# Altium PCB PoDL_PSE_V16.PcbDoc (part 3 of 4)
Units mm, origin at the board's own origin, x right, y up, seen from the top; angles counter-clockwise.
Board outline 155 x 86.5 mm, 4 copper layers (Top Layer, Signal Layer 2, Signal Layer 3, Bottom Layer), stack 1.586 mm thick; 431 components, 281 nets, 1286 pads, 864 vias.
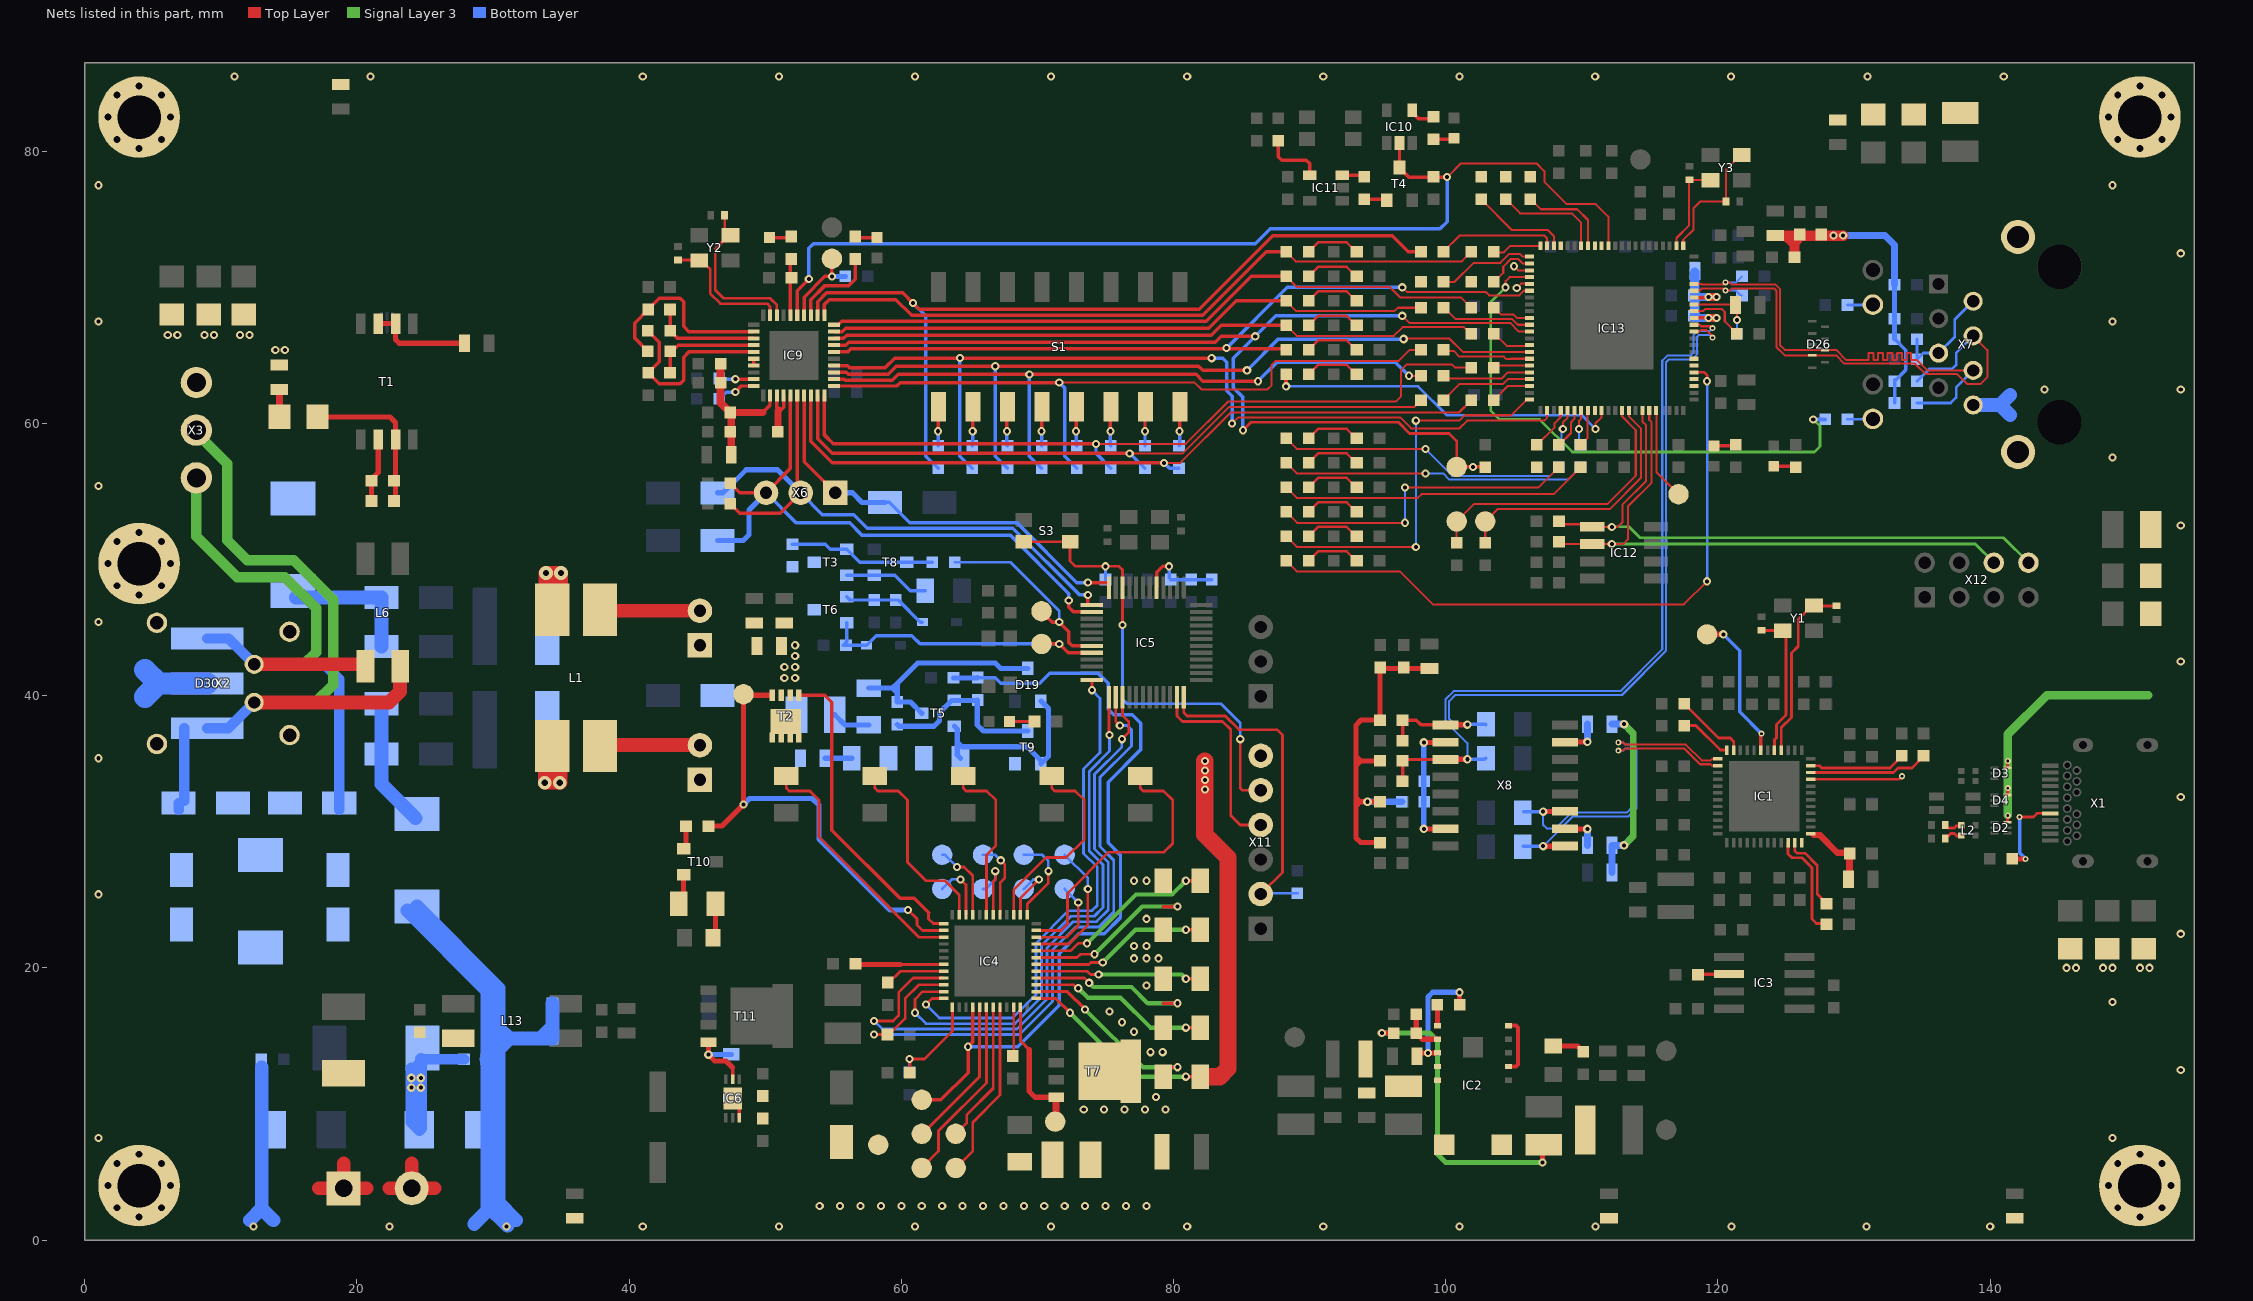
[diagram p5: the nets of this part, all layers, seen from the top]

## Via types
v1: diameter 0.6, hole 0.3, Top Layer to Bottom Layer, tented both sides, 494 vias
v2: diameter 0.45, hole 0.2, Top Layer to Bottom Layer, tented both sides, 173 vias
v3: diameter 0.635, hole 0.3, Top Layer to Bottom Layer, tented both sides, 145 vias
v4: diameter 1.016, hole 0.508, Top Layer to Bottom Layer, 40 vias
v5: diameter 1.016, hole 0.457, Top Layer to Bottom Layer, tented both sides, 8 vias
v6: diameter 0.762, hole 0.381, Top Layer to Bottom Layer, tented both sides, 4 vias

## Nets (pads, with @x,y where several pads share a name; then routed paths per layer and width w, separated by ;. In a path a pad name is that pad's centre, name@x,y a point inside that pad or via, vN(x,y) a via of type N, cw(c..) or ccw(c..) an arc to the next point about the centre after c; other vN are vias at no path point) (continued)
GPIO4: IC13.27 | length 1
  Top Layer w0.147: v1(105.218,69.945) 105.54,70.266 IC13.27@106.134,70.266
GPIO5: IC13.26 R91.2 | length 40.5
  Top Layer w0.152: v1(104.4,70) 104.4,70.45 104.7,70.75 IC13.26@106.15,70.75
  Signal Layer 3 w0.203: v1(104.4,70) 103.3,68.9 103.3,60.935 103.935,60.3 106.9,60.3 109.3,57.9 127.1,57.9 127.5,58.3 127.5,59.8 v1(127,60.3)
  Bottom Layer w0.3: v1(127,60.3) R91.2@127.874,60.3
GPIO6: IC13.14
GPIO7: IC13.13
HGATE0: HGATE0.1 IC4.2 R35.2 T2.4 | length 34.2
  Top Layer w0.203: v1(60.5,24.25) 61.141,23.608 61.141,23.158 61.55,22.75 IC4.2@63.1,22.75
  Top Layer w0.381: R35.2@45.825,30.4 45.8,30.425 46.825,30.425 v1(48.4,32) 48.4,40 48.5,40.1 48.57,40.03 T2.4@50.525,40.03
  Bottom Layer w0.381: v1@48.4,32.1 v1(48.4,32) 48.85,32.45 53.434,32.45 53.944,31.94 53.944,29.462 59.156,24.25 v1(60.5,24.25)
I2C2_SCL: IC12.6 IC13.61 R85.2 X12.6 | length 44.1
  Top Layer w0.152: R85.2@108.326,51.3 108.491,51.135 IC12.6@110.76,51.135 v1(112.2,51.135) 113.035,51.135 113.381,51.481 113.381,53.892 115.102,55.613 115.102,60.12 114.95,60.272 IC13.61@114.95,60.95
  Signal Layer 3 w0.203: v1(112.2,51.135) 138.905,51.135 X12.6@140.27,49.77
I2C2_SDA: IC12.5 IC13.60 R86.2 X12.8 | length 45.2
  Top Layer w0.152: IC12.5@111,52.405 112.645,52.405 113,52.76 113,54.05 114.721,55.771 114.721,59.874 114.45,60.145 IC13.60@114.45,60.95
  Top Layer w0.178: R86.2@108.326,52.8 108.526,52.6 IC12.5@110.565,52.6
  Signal Layer 3 w0.203: v1(112.2,52.4) 113.483,52.4 114.283,51.6 140.98,51.6 X12.8@142.81,49.77
I\N\T\: D7.2 IC5.14 IC9.25 R70.2 X6.3 | length 45.6
  Top Layer w0.254: R70.2@47.426,55.6 48.125,54.9 X6.3@50.06,54.9 51.85,56.69 IC9.25@51.85,62.05 ; v1(72.3,47) 72.3,46.496 72.646,46.15 IC5.14@73.975,46.15
  Bottom Layer w0.254: X6.3@50.06,54.9 52.26,52.7 56.2,52.7 57.1,51.8 68,51.8 72.3,47.5 v1(72.3,47)
  Bottom Layer w0.381: D7.2@46.5,51.4 48.38,51.4 48.8,51.82 48.8,53.64 X6.3@50.06,54.9 X6.3@50.06,54.36
IRQ: IC13.62 TP6.1 | length 6.8
  Top Layer w0.152: IC13.62@115.483,60.917 115.483,56.417 TP6.1@117.1,54.8
LED2: IC1.24
LED3: IC1.33 | length 6.8
  Top Layer w0.203: IC1.33@126.8,33.85 133.295,33.85 v2(133.525,34.08)
LINK_ST: IC9.4 R60.1 TP4.1 | length 6.3
  Top Layer w0.254: IC9.4@52.85,67.95 52.85,69.276 54.374,70.8 v1(54.9,70.8) TP4.1@54.9,72.1
  Bottom Layer w0.381: v1(54.9,70.8) R60.1@55.875,70.8
LSNS: C38.1 D9.1 IC4.26 IC4.28 IC4.31 LSNS.1 R24.1 RSL0.1 RSL1.1 RSL2.1 RSL3.1 RSL4.1 T7.mb | length 39
  Top Layer w0.203: IC4.28@69.9,19.25 73.45,19.25 v1(73.8,18.9) ; IC4.31@69.9,20.75 72.9,20.75 73.15,21 v1(74.2,21)
  Top Layer w0.229: IC4.26@69.9,18.25 72.2,18.25 v1(73.5,16.95)
  Top Layer w0.254: RSL0.1@79.25,12.7 v1(80.3,12.7) ; 79.25,17.4 v1(80.3,17.4) ; 79.25,24.5 v1(80.3,24.5)
  Signal Layer 3 w0.305: v1(73.5,16.95) 77.75,12.7 v1(80.3,12.7) ; v1(73.8,18.9) 74.1,18.6 76.9,18.6 78.1,17.4 v1(80.3,17.4) ; v1(74.2,21) 77.7,24.5 v1(80.3,24.5)
  other v1: 54,2.5 55.5,2.5 57,2.5 58.5,2.5 60,2.5 61.5,2.5 63,2.5 64.5,2.5 66,2.5 67.5,2.5 69,2.5 70.5,2.5 72,2.5 73.5,2.5 75,2.5 76.5,2.5 78,2.5 73.4,9.6 74.9,9.6 76.4,9.6 77.9,9.6 79.4,9.6 78.7,10.5 78.3,13.8 79.2,13.8 77.1,15.3 76.2,16 75.3,16.8 78,18.7 77.1,20.7 78,20.7 78.9,20.7 77.1,21.6 78,21.6 78,23.6 77.1,26.4 78,26.4
MDC: D6.2 IC5.12 IC9.27 X6.1 | length 31.2
  Top Layer w0.254: IC9.27@52.85,62.05 52.85,57.19 X6.1@55.14,54.9 ; v1(73.7,48.3) IC5.12@75.256,48.3
  Bottom Layer w0.254: D6.2@58.8,54.2 59.125,54.2 60.625,52.7 68.5,52.7 72.9,48.3 v1(73.7,48.3)
  Bottom Layer w0.381: X6.1@55.14,55.15 X6.1@55.14,54.9 ; X6.1@55.145,54.895 X6.1@55.14,54.9 ; D6.2@58.8,54.2 57.1,54.2 56.4,54.9 X6.1@55.14,54.9
MDIO: D8.2 IC5.13 IC9.26 R71.2 X6.2 | length 45.8
  Top Layer w0.254: R71.2@47.426,54.1 48.126,53.4 51.1,53.4 X6.2@52.6,54.9 ; X6.2@52.35,54.8 IC9.26@52.35,62.05 ; IC5.13@73.7,46.65 v1(73.7,47.4)
  Bottom Layer w0.254: X6.2@52.6,54.9 54.2,53.3 56.5,53.3 57.5,52.3 68.186,52.3 73.086,47.4 v1(73.7,47.4)
  Bottom Layer w0.381: D8.2@46.5,54.9 46.9,54.9 48.6,56.6 50.9,56.6 X6.2@52.6,54.9
NetC1_2: C1.2 IC4.7 | length 6.5
  Top Layer w0.203: 59.924,20.25 IC4.7@63.1,20.25
  Top Layer w0.381: C1.2@56.625,20.3 56.675,20.25 59.924,20.25
NetC7_1: C7.1 L2.3 | length 1.3
  Top Layer w0.206: C7.1@136.7,30.5 136.93,30.27 137.372,30.27 137.547,30.445 L2.3@137.875,30.445
NetC8_1: C8.1 L2.2 | length 1.4
  Top Layer w0.206: C8.1@136.7,29.47 137.1,29.87 137.372,29.87 137.547,29.695 L2.2@137.875,29.695
NetC9_1: C9.1 FB3.1 IC1.25 | length 8
  Top Layer w0.254: C9.1@129.374,28.355 128.725,28.355 127.419,29.661 126.989,29.661 IC1.25@126.8,29.85 127.536,29.85 128.806,28.58 C9.1@129.5,28.58
  Top Layer w0.508: FB3.1@129.675,26.805 C9.1@129.675,28.405
NetC26_1: C26.1 C123.1 IC2.4 IC2.5 L11.2
NetC29_1: C29.1 IC1.48 | length 4
  Top Layer w0.2: C29.1@117.426,37.805 118.37,37.805 120.175,36 IC1.48@120.65,36
NetC30_2: C30.2 IC1.40 Y1.1 | length 13.2
  Top Layer w0.203: IC1.40@124.65,36 124.65,37.654 125.4,38.404 125.4,43.13 125.9,43.63 125.9,45.605 Y1.1@126.8,46.505 ; Y1.1@126.9,46.58 C30.2@128.7,46.58
NetC31_2: C31.2 IC1.41 Y1.3 | length 10.7
  Top Layer w0.203: C31.2@123.2,44.78 Y1.3@124.725,44.78 ; IC1.41@124.15,36 124.15,36.755 124.3,36.905 124.3,37.87 125,38.57 Y1.3@125,44.805
NetC32_1: C32.1 IC4.8 | length 4.3
  Top Layer w0.203: C32.1@59.1,18.925 59.924,19.75 IC4.8@63.1,19.75
NetC33_1: C33.1 C119.1 T1.6 | length 4.7
  Top Layer w0.381: C119.1@21.074,54.3 C33.1@21.074,55.8 21.074,55.909 21.565,56.4 T1.6@21.565,58.82
NetC33_2: C33.2 C42.1 C119.2 T1.7 | length 11.8
  Top Layer w0.381: C42.1@17.1,60.1 17.47,60.47 22.435,60.47 22.835,60.07 T1.7@22.835,58.82 C119.2@22.835,54.3
NetC34_2: C34.2 R13.1 | length 2
  Bottom Layer w0.381: C34.2@54.4,35.4 R13.1@56.35,35.4
NetC35_2: C35.2 R14.1 | length 2.8
  Bottom Layer w0.381: C35.2@55.1,38.6 55.85,37.85 R14.1@57.6,37.85
NetC36_1: C36.1 R27.1 T3.1 T8.3 | length 10.8
  Bottom Layer w0.254: C36.1@52,51.126 54.4,51.126 54.776,50.75 T3.1@56,50.75 56.95,49.8 T8.3@60.4,49.8 R27.1@62.275,49.8
NetC37_1: C37.1 T1.2 T1.3 | length 7.6
  Top Layer w0.381: T1.3@21.57,67.341 22.84,67.341 22.84,66.156 23.105,65.891 C37.1@27.9,65.891
NetC38_2: C38.2 R25.1
NetC39_1: C39.1 R30.2 T5.1 T9.3 | length 12.8
  Bottom Layer w0.381: C39.1@59.7,37.875 59.824,37.75 62.4,37.75 62.8,38.15 62.8,38.75 63.7,39.65 T5.1@63.9,39.65 R30.2@65.575,39.65 ; R30.2@65.6,39.675 R30.2@65.575,39.65 ; T9.3@69.3,37.4 66.025,37.4 65.575,37.85 R30.2@65.575,39.65
NetC39_2: C39.2 D19.3 R14.2 T5.3 | length 16.6
  Bottom Layer w0.381: R14.2@57.6,40.55 59.35,40.55 ; T5.3@61.5,38.7 60.674,39.526 C39.2@59.7,39.526 59.7,40.2 ; D19.3@69.3,42 67.3,42 66.9,42.4 61.2,42.4 59.7,40.9 ; 59.35,40.55 59.7,40.2 ; 59.35,40.55 59.7,40.9 ; 59.7,40.2 59.7,40.9
NetC42_2: C42.2 R42.1 | length 2
  Top Layer w0.508: C42.2@14.3,60.5 R42.1@14.3,62.5
NetC45_1: C45.1 C52.1 FB9.1 IC5.5 | length 6.3
  Top Layer w0.254: IC5.5@78.75,47.925 78.75,49.05 79.2,49.5 v1(79.675,49.5)
  Bottom Layer w0.254: v1(79.675,49.5) 79.675,48.651 C45.1@79.8,48.526 C52.1@81.3,48.526 FB9.1@82.8,48.526
NetC55_2: C55.2 IC9.8 Y2.1 | length 11.9
  Top Layer w0.203: C55.2@47.025,75.3 47.025,74.25 Y2.1@47.45,73.825 47.325,73.825 46.325,72.825 46.325,69.8 46.925,69.2 50.35,69.2 50.85,68.7 IC9.8@50.85,67.95
NetC56_2: C56.2 IC9.9 Y2.3 | length 9.8
  Top Layer w0.203: C56.2@43.6,72 Y2.3@45.3,72 ; Y2.3@45.325,71.975 45.95,71.35 45.95,69.55 46.7,68.8 50.15,68.8 50.35,68.6 IC9.9@50.35,67.95
NetC57_1: C57.1 C58.1 C63.1 C64.1 FB1.2 IC9.16 IC9.17 IC9.22 | length 11.3
  Top Layer w0.254: IC9.17@49.15,64.25 IC9.16@49.15,64.75 ; 49.825,60.8 50.35,61.325 IC9.22@50.35,62.05
  Top Layer w0.508: C63.1@47.426,60.8 49.825,60.8
  Top Layer w0.584: C58.1@46.725,64.4 C57.1@46.725,63 46.725,61.5 C63.1@47.426,60.8 ; FB1.2@47.5,57.7 C63.1@47.5,60.726
NetC59_1: C59.1 IC9.19 | length 2.5
  Top Layer w0.254: v1(47.8,63.25) IC9.19@49.15,63.25
  Bottom Layer w0.254: C59.1@46.675,63.25 v1(47.8,63.25)
NetC60_1: C60.1 IC9.20 | length 2.9
  Top Layer w0.254: v1(47.8,62.3) 48.25,62.75 IC9.20@49.15,62.75
  Bottom Layer w0.254: C60.1@46.625,61.8 47.125,62.3 v1(47.8,62.3)
NetC65_1: C65.1 IC9.23 IC9.24 | length 4
  Top Layer w0.254: IC9.23@50.85,62.05 50.85,61.15 51,61 51.174,61 51.35,61.176 IC9.24@51.35,62.05
  Top Layer w0.508: C65.1@50.926,59.4 50.925,60.926 51,61
NetC77_1: C77.1 FB2.2 IC13.81 | length 5.1
  Top Layer w0.152: IC13.81@118.258,68.75 FB2.2@121.25,68.75 ; FB2.2@121.374,68.8 121.4,68.775 v1(121.4,67.6)
  Bottom Layer w0.152: C77.1@121.4,66.726 v1(121.4,67.6)
NetC80_1: C80.1 C81.1 FB5.1 IC13.79 IC13.82 | length 9.9
  Top Layer w0.254: IC13.79@118.308,67.75 v1(119.3,67.75) ; IC13.82@118.308,69.25 v1@119.3,69.25
  Top Layer w0.6: v1(119.3,67.75) v1(119.9,67.75) ; v1(119.3,69.3) v1(119.9,69.3)
  Bottom Layer w0.6: C81.1@118.225,67.8 118.275,67.75 v1(119.3,67.75) v1(119.9,67.75) ; C80.1@118.225,69.3 118.275,69.25 C80.1@118.3,69.25 ; C80.1@118.3,69.3 v1(119.3,69.3) v1(119.9,69.3)
  Bottom Layer w0.7: C81.1@118.225,67.8 118.3,67.875 118.3,69.25 FB5.1@118.3,71.1
NetC82_2: C82.2 IC13.1 Y3.1 | length 9.5
  Top Layer w0.152: IC13.1@117.45,73.05 117.45,73.483 118.203,74.236 118.203,75.82 118.683,76.3 C82.2@120.6,76.3 120.6,78.65 Y3.1@121.675,79.725
NetC83_2: C83.2 IC13.2 Y3.3 | length 6.8
  Top Layer w0.152: IC13.2@116.95,73.05 116.95,73.623 117.879,74.552 C83.2@117.879,77.9 ; C83.2@117.9,77.9 Y3.3@119.425,77.9
NetC89_1: C89.1 R81.1 X7.P2 X7.P5 | length 8.2
  Bottom Layer w0.203: R81.1@134.625,66.2 C89.1@134.625,64.7 135.09,65.165 X7.P5@136.21,65.165 ; X7.P5@136.145,65.1 X7.P5@136.21,65.165 ; X7.P2@138.75,68.975 137.4,67.625 137.4,66.355 X7.P5@136.21,65.165
NetC97_2: C97.2 C107.1 D1.1 D29.1 L13.1 X4.2 | length 19.8
  Top Layer w1.016: 22.4,3.8 X4.2@24.025,3.8 ; 24.025,5.625 X4.2@24.025,3.8 ; 25.7,3.8 X4.2@24.025,3.8
  Bottom Layer w0.762: D1.1@24.975,13.279 C107.1@27.875,13.279
  Bottom Layer w0.889: D1.1@24,12.6 24,12.3 ; D1.1@24.7,13.3 D1.1@24.7,13 ; D1.1@24.8,13.1 D1.1@24.7,13 ; v3(24,11.2) v3(24,11.9) 24,12.3 ; v3(24,11.2) v3(24.7,11.2) ; v3(24,11.2) 24,8.69 D29.1@24.59,8.1 24.7,8.21 v3(24.7,11.2) ; 24,12.3 D1.1@24.7,13 ; v3(24.7,11.2) v3(24.7,11.9) D1.1@24.7,13
NetC98_1: C98.1 R153.1 X8.10 X8.15 | length 9.5
  Top Layer w0.381: v3(98.389,30.206) X8.15@99.971,30.206 ; v3(98.389,36.556) X8.10@99.971,36.556
  Bottom Layer w0.381: v3(98.389,30.206) v3(98.389,36.556)
NetC103_1: C103.1 R158.1 R159.1 | length 13.3
  Signal Layer 3 w0.508: v3(113.101,29) 113.776,29.675 113.776,37.225 v3(113.101,37.9)
  Bottom Layer w0.508: C103.1@112.201,27 R158.1@112.201,29 ; R158.1@112.2,29 v3(113.101,29) ; R159.1@112.2,37.9 v3(113.101,37.9)
NetC111_2: C111.2 FB10.2 X5.1
NetC112_1: C112.1 C113.1 C126.1 R77.2 R78.2 R79.2 R80.2 R81.2 R162.2 | length 24.9
  Top Layer w0.762: C126.1@124.2,73.8 124.997,73.8 ; R162.2@125.625,72.2 125.625,73.5 125.461,73.336 124.997,73.8 ; 125.7,73.4 C112.1@126,73.7 ; C112.1@126,73.875 C112.1@125.925,73.8 ; v1(129.2,73.8) v1(128.5,73.8) 127.6,73.8 C112.1@125.925,73.8 ; 124.997,73.8 C112.1@125.925,73.8
  Bottom Layer w0.254: R80.2@132.974,61.5 R79.2@132.974,63.1 ; R79.2@132.974,63.2 R79.2@132.974,63.1 ; R81.2@132.974,66.2 133.8,65.375 133.8,63.925 R79.2@132.974,63.1
  Bottom Layer w0.381: R81.2@132.974,66.2 R78.2@132.974,67.7 R77.2@132.974,70.2
  Bottom Layer w0.508: v1(128.5,73.8) v1(129.2,73.8) 132.283,73.8 132.974,73.109 R77.2@132.974,70.2
NetC114_1: C114.1 C115.1 FB8.1 R153.2 R154.2 R155.2 R156.2 R157.2 | length 26.7
  Top Layer w0.381: R154.2@95.175,29.2 93.751,29.2 93.401,29.55 93.401,31.9 ; R155.2@95.175,32.2 v3(94.251,32.2) 93.701,32.2 ; R156.2@95.175,35.2 93.751,35.2 ; C114.1@95.175,41.949 95.175,38.2 93.779,38.2 93.401,37.821 93.401,35.55 ; C114.1@95.275,42 FB8.1@98.8,42 ; 93.401,31.9 93.701,32.2 ; 93.401,31.9 93.401,32.5 ; 93.401,32.5 93.401,34.85 ; 93.401,32.5 93.701,32.2 ; 93.401,34.85 93.751,35.2 ; 93.401,34.85 93.401,35.55 ; 93.401,35.55 93.751,35.2
  Bottom Layer w0.508: v3(94.251,32.2) R153.2@96.775,32.2
NetC117_1: C117.1 D14.1 R31.2 T6.1 | length 6.3
  Bottom Layer w0.254: T6.1@56,47.25 56.224,47.026 C117.1@58,47.026 R31.2@59.6,47.026 59.775,47.026 61.4,45.4 D14.1@61.55,45.4
NetC122_2: C122.2 IC6.6 IC6.7 R43.1 | length 1.6
  Top Layer w0.254: IC6.7@47.6,10.4 48.1,9.9 IC6.6@48.1,9
NetC124_1: C124.1 IC2.6 IC2.7 L12.1 R10.2 | length 22.8
  Top Layer w0.381: v1(95.3,15.2) R10.2@96.174,15.2 ; v1(107.1,5.7) 107.1,6.9 C124.1@107.2,7
  Signal Layer 3 w0.381: v1(95.3,15.2) 98.8,15.2 99.4,14.6 99.4,6.3 100,5.7 v1(107.1,5.7)
NetC125_1: C125.1 IC2.3 R28.2 | length 9.1
  Top Layer w0.381: C125.1@97.9,13.5 98.15,13.75 v1(98.7,13.75) IC2.3@99.4,13.75 ; v1(101,18.2) 101,17.325 R28.2@101.026,17.3
  Bottom Layer w0.381: v1(98.7,13.75) 98.7,17.856 99.044,18.2 v1(101,18.2)
NetD5_2: D5.2 R4.2 | length 2.4
  Top Layer w0.381: D5.2@107.9,14.25 109.676,14.25 R4.2@110.1,13.825
NetD11_1: D11.1 D13.2 D16.1
NetD12_2: D12.2 D13.1 D15.2
NetD19_1: D19.1 R32.1 T5.2 T9.1 | length 14.5
  Bottom Layer w0.381: T5.2@63.9,37.75 64.1,37.55 64.1,36.6 ; R32.1@64.35,35.4 64.1,35.65 64.1,36.6 ; D19.1@70.25,39.6 70.8,39.05 70.8,35.55 T9.1@70.25,35 70.25,35.212 69.222,36.24 64.46,36.24 64.1,36.6
NetD20_2: D20.2 R36.1 | length 2.6
  Top Layer w0.381: D20.2@46.15,22.2 46.35,22.4 R36.1@46.35,24.7
NetD21_2: D21.2 R40.2 | length 1.7
  Top Layer w0.254: D21.2@68.05,38.1 R40.2@69.775,38.1
NetD23_1: D23.1 R62.1 | length 1.5
  Top Layer w0.254: D23.1@50.3,73.65 R62.1@51.825,73.65
NetD24_1: D24.1 R63.2 | length 1.5
  Top Layer w0.254: R63.2@56.675,73.65 D24.1@58.2,73.65
NetD25_2: D25.2 R74.2 | length 1.4
  Top Layer w0.254: R74.2@99.1,80.875 D25.2@100.525,80.875
NetD27_2: D27.2 R92.2 | length 1.6
  Top Layer w0.25: D27.2@124.1,56.85 125.624,56.85 R92.2@125.7,56.775
NetD28_2: D28.2 R93.2 | length 1.5
  Top Layer w0.25: D28.2@119.7,58.35 R93.2@121.224,58.35
NetD31_2: D31.2 D32.1 D33.2 | length 9.9
  Bottom Layer w1.016: D33.2@15.5,47.2 D31.2@21.8,47.2 D32.1@21.8,43.6
NetD34_2: D34.2 D35.1 D36.2 | length 9.4
  Bottom Layer w1.016: D34.2@21.8,39.4 D35.1@21.8,35.7 21.8,33.496 D36.2@24.3,30.996
NetF1_1: F1.1 X4.1 | length 5.3
  Top Layer w1.016: 17.2,3.8 X4.1@19.025,3.8 ; 19.025,5.625 X4.1@19.025,3.8 ; 20.7,3.8 X4.1@19.025,3.8
NetHGATE1_1: HGATE1.1 IC4.46 | length 4.4
  Top Layer w0.203: v1(64.35,26.5) 64.75,26.1 IC4.46@64.75,23.9
  Bottom Layer w0.203: HGATE1.1@63,25.8 63.7,26.5 v1(64.35,26.5)
NetHGATE2_1: HGATE2.1 IC4.42 | length 4.9
  Top Layer w0.203: IC4.42@66.75,23.9 66.75,26.35 66.944,26.544 v1@66.944,26.956
  Bottom Layer w0.203: HGATE2.1@66,25.8 66.2,25.8 66.9,26.5 v1(66.9,27.1)
NetHGATE3_1: HGATE3.1 IC4.38 | length 4.5
  Top Layer w0.203: IC4.38@68.75,23.9 68.75,25.125 70.1,26.475 v1(70.1,26.5)
  Bottom Layer w0.203: HGATE3.1@69,25.8 69.7,26.5 v1(70.1,26.5)
NetHGATE4_1: HGATE4.1 IC4.34 | length 6.6
  Top Layer w0.203: IC4.34@69.9,22.25 72.14,22.25 73,23.11 v1(73,24.8)
  Bottom Layer w0.203: HGATE4.1@72,25.8 v1(73,24.8)
NetIC1_23: IC1.23 R5.2 | length 5.8
  Top Layer w0.203: IC1.23@125.65,29.2 125.65,28.586 125.811,28.425 126.399,28.425 127.288,27.536 127.288,25.442 R5.2@127.975,24.755
NetIC1_35: IC1.35 R6.2 | length 7.2
  Top Layer w0.203: IC1.35@126.8,34.85 127.45,34.85 127.62,34.68 132.651,34.68 R6.2@133.525,35.555
NetIC1_47: IC1.47 R7.1 | length 5.4
  Top Layer w0.2: R7.1@117.526,39.4 120.045,36.881 120.905,36.881 121.15,36.635 IC1.47@121.15,36
NetIC2_1: IC2.1 R28.1 | length 1.6
  Top Layer w0.381: R28.1@99.275,17.3 R28.1@99.3,17.274 ; IC2.1@99.4,15.75 R28.1@99.4,17.274
NetIC2_2: IC2.2 R10.1 R34.1 | length 3.2
  Top Layer w0.381: R34.1@97.825,16.6 R10.1@97.825,15.2 98.276,14.75 IC2.2@99.4,14.75
NetIC2_9: IC2.9 IC2.12 | length 4.2
  Top Layer w0.305: IC2.9@104.6,12.75 105.15,12.75 105.3,12.9 105.3,15.6 105.15,15.75 IC2.12@104.6,15.75
NetIC3_6: IC3.6 R17.1 | length 2.2
  Top Layer w0.254: R17.1@118.56,19.535 IC3.6@120.8,19.535
NetIC4_3: IC4.3 RSH0.2 T2.mb | length 18.6
  Top Layer w0.203: RSH0.2@51.55,34.1 51.55,33.2 51.75,33 53.27,33 53.944,32.326 53.944,29.606 61.3,22.25 IC4.3@63.1,22.25
NetIC4_13: IC4.13 R37.2 R38.2 | length 7.6
  Top Layer w0.203: v1@60.589,13.3 61.7,13.3 63.75,15.35 IC4.13@63.75,17.1 ; R37.2@60.625,12.3 v1@60.625,13.163
  Bottom Layer w0.203: v1(60.6,13.3) 60.6,12.426 R38.2@60.7,12.326
NetIC4_16: IC4.16 R16.2 R30.1 SW0.1 | length 59.1
  Top Layer w0.254: SW0.1@61.5,10.3 62.9,10.3 64.9,12.3 v1(64.9,14.2) 65.25,14.55 IC4.16@65.25,17.1
  Bottom Layer w0.254: v1(64.9,14.2) 68.562,14.2 71.6,17.238 71.6,21.05 73.042,22.492 74.892,22.492 76.1,23.7 76.1,28.268 75.186,29.182 75.186,33.636 77.589,36.039 77.589,37.974 76.963,38.6 75.6,38.6 75.2,39 75.2,40.9 74.45,41.65 70.912,41.65 70.162,40.9 67.311,40.9 66.886,41.326 R30.1@65.6,41.326
  Bottom Layer w0.381: R16.2@63.825,41.3 65.574,41.3 R30.1@65.6,41.326
NetIC4_17: IC4.17 SW1.1 | length 11.1
  Top Layer w0.203: SW1.1@61.525,7.775 65.75,12 IC4.17@65.75,17.1
NetIC4_18: IC4.18 SW2.1 | length 13.8
  Top Layer w0.203: SW2.1@61.5,5.3 62.73,6.53 62.73,8.03 66.25,11.55 IC4.18@66.25,17.1
NetIC4_19: IC4.19 SW3.1 | length 10.4
  Top Layer w0.203: SW3.1@64,7.8 64.8,8.6 64.8,9.2 66.75,11.15 IC4.19@66.75,17.1
NetIC4_20: IC4.20 SW4.1 | length 13.1
  Top Layer w0.203: SW4.1@64,5.3 65.25,6.55 65.25,8.65 67.25,10.65 IC4.20@67.25,17.1
NetIC4_22: IC4.22 R9.1 | length 3.6
  Top Layer w0.203: R9.1@68.25,13.5 IC4.22@68.25,17.1
NetIC4_23: IC4.23 LGATE.1 T7.4 | length 10.4
  Top Layer w0.229: IC4.23@68.75,17.1 68.75,14.64 69.397,13.993
  Top Layer w0.381: 69.397,13.993 69.397,10.923 69.825,10.495 T7.4@71.375,10.495
  Top Layer w0.508: LGATE.1@71.3,8.7 71.375,8.775 T7.4@71.375,10.495
NetIC4_27: IC4.27 RSL1.2 | length 13.4
  Top Layer w0.203: IC4.27@69.9,18.75 72.65,18.75 v1@73,18.4
  Top Layer w0.254: v1(80.9,15.6) RSL1.2@81.95,15.6
  Signal Layer 3 w0.305: v1(73,18.5) 73.7,17.8 76.1,17.8 78.3,15.6 v1(80.9,15.6)
NetIC4_29: IC4.29 RSL2.2 | length 12.3
  Top Layer w0.203: IC4.29@69.9,19.75 73.654,19.75 73.904,19.5 v1(74.5,19.5)
  Top Layer w0.254: v1(80.9,19.2) RSL2.2@81.95,19.2
  Signal Layer 3 w0.305: v1(74.5,19.5) 80.6,19.5 v1(80.9,19.2)
NetIC4_30: IC4.30 RSL3.2 | length 13.1
  Top Layer w0.203: IC4.30@69.9,20.25 73.771,20.25 73.921,20.4 v1(74.8,20.4)
  Top Layer w0.254: v1(80.9,22.8) RSL3.2@81.95,22.8
  Signal Layer 3 w0.305: v1(74.8,20.4) 77.2,22.8 v1(80.9,22.8)
NetIC4_32: IC4.32 RSL4.2 | length 14.2
  Top Layer w0.203: IC4.32@69.9,21.25 72.44,21.25 72.99,21.8 v1(73.65,21.8)
  Top Layer w0.254: v1(80.9,26.4) RSL4.2@81.95,26.4
  Signal Layer 3 w0.305: v1(73.65,21.8) 77.25,25.4 79.9,25.4 v1(80.9,26.4)
NetIC4_33: IC4.33 OUTP4.1 | length 10.2
  Top Layer w0.203: IC4.33@69.9,21.75 72.3,21.75 73.7,23.15 v1(73.7,25.8)
  Bottom Layer w0.203: OUTP4.1@72,28.3 73.7,26.6 v1(73.7,25.8)
NetIC4_35: IC4.35 RSH4.2 | length 20.9
  Top Layer w0.203: IC4.35@69.9,22.75 71.74,22.75 72.2,23.21 72.2,25.474 75.225,28.5 79.3,28.5 79.944,29.144 79.944,32.326 79.27,33 77.75,33 77.55,33.2 RSH4.2@77.55,34.1
NetIC4_37: IC4.37 OUTP3.1 | length 6.8
  Top Layer w0.203: IC4.37@69.25,23.9 69.25,24.675 70.8,26.225 70.8,26.957 70.657,27.1 v1(70.8,27.1)
  Bottom Layer w0.203: OUTP3.1@69,28.3 70.355,28.3 70.8,27.855 v1(70.8,27.1)
NetIC4_39: IC4.39 RSH3.2 | length 15.1
  Top Layer w0.203: IC4.39@68.25,23.9 68.25,25.724 70.625,28.1 72.107,28.1 73.444,29.436 73.444,32.326 72.77,33 71.25,33 71.05,33.2 RSH3.2@71.05,34.1
NetIC4_41: IC4.41 OUTP2.1 | length 5.7
  Top Layer w0.203: IC4.41@67.25,23.9 67.274,23.924 67.274,26.274 67.6,26.6 67.6,27.6 v1(67.3,27.9)
  Bottom Layer w0.203: OUTP2.1@66,28.3 66.9,28.3 v1(67.3,27.9)
NetIC4_43: IC4.43 RSH2.2 | length 12.4
  Top Layer w0.203: RSH2.2@64.55,34.1 64.55,33.2 64.75,33 66.27,33 66.944,32.326 66.944,28.994 66.25,28.3 IC4.43@66.25,23.9
NetIC4_45: IC4.45 OUTP1.1 | length 5.8
  Top Layer w0.203: v1(64.1,27.4) 64.617,27.4 65.25,26.767 IC4.45@65.25,23.9
  Bottom Layer w0.203: OUTP1.1@63,28.3 63.2,28.3 v1(64.1,27.4)
NetIC4_47: IC4.47 RSH1.2 | length 14.5
  Top Layer w0.203: RSH1.2@58.05,34.1 58.05,33.2 58.25,33 59.77,33 60.444,32.326 60.444,27.756 61.8,26.4 63.207,26.4 64.25,25.357 IC4.47@64.25,23.9
NetIC6_2: IC6.2 T11.4 Z1.1 | length 5.6
  Top Layer w0.254: IC6.2@47.6,11.8 47.6,12.675
  Top Layer w0.381: T11.4@45.825,14.545 v3(45.825,13.625) 46.287,13.163 47.112,13.163 47.6,12.675
  Bottom Layer w0.381: v3(45.825,13.625) 47.488,13.625 Z1.1@47.5,13.638
NetIC9_3: IC9.3 R63.1 | length 6.5
  Top Layer w0.254: IC9.3@53.35,67.95 53.35,69.1 54.35,70.1 56.1,70.1 56.6,70.6 R63.1@56.6,72.075
NetIC9_6: IC9.6 R61.1 R62.2 | length 4.1
  Top Layer w0.254: IC9.6@51.85,67.95 R62.2@51.85,72.025
NetIC9_12: IC9.12 R64.2 R66.1 | length 14.1
  Top Layer w0.254: R66.1@41.374,65.3 40.4,66.275 40.4,67.375 R64.2@41.4,68.375 42.225,69.2 43.735,69.2 44,68.935 44,67.125 44.375,66.75 IC9.12@49.15,66.75
NetIC9_13: IC9.13 R65.2 R67.1 | length 7.6
  Top Layer w0.254: R67.1@43.025,66.8 R65.2@43.025,68.349 ; R67.1@43.2,66.6 43.55,66.25 IC9.13@49.15,66.25
NetIC9_14: IC9.14 R66.2 R68.2 | length 7.7
  Top Layer w0.254: R68.2@43.025,63.751 R66.2@43.025,65.3 ; R66.2@43.15,65.3 43.6,65.75 IC9.14@49.15,65.75
NetIC9_15: IC9.15 R67.2 R69.2 | length 13.8
  Top Layer w0.254: R67.2@41.374,66.8 42.2,65.974 42.2,64.526 R69.2@41.4,63.726 42.226,62.9 43.735,62.9 44,63.165 44,64.864 44.386,65.25 IC9.15@49.15,65.25
NetIC10_4: IC10.4 R74.1 | length 1.6
  Top Layer w0.254: IC10.4@97.55,82.85 98,82.4 R74.1@98.975,82.4
NetIC11_3: IC11.3 R76.1 | length 1.5
  Top Layer w0.254: IC11.3@92.4,78.25 R76.1@93.875,78.25
NetIC11_4: IC11.4 R75.2 | length 4.5
  Top Layer w0.254: R75.2@87.7,80.775 87.7,79.6 87.95,79.35 89.75,79.35 90,79.1 IC11.4@90,78.25
NetIC13_15: IC13.15 R112.1 | length 6.8
  Top Layer w0.147: R112.1@106.231,76.498 106.993,75.736 109.66,75.736 110.45,74.946
  Top Layer w0.152: IC13.15@110.45,73.05 110.45,74.946
NetIC13_16: IC13.16 R113.1 | length 7.9
  Top Layer w0.152: R113.1@104.434,76.474 105.474,75.434 109.262,75.434 109.95,74.745 IC13.16@109.95,73.05
NetIC13_20: IC13.20 R120.1 | length 7.2
  Top Layer w0.152: R120.1@102.6,76.475 104.862,74.212 107.499,74.212 107.95,73.761 IC13.20@107.95,73.05
NetIC13_21: IC13.21 R131.2 | length 8.8
  Top Layer w0.152: R131.2@99.826,72.6 101.032,73.807 107.228,73.807 107.45,73.585 IC13.21@107.45,73.05
NetIC13_22: IC13.22 R130.2 | length 3.6
  Top Layer w0.152: R130.2@103.572,72.564 104.264,72.564 104.75,73.05 IC13.22@106.95,73.05
NetIC13_23: IC13.23 R115.1 | length 7.2
  Top Layer w0.147: R115.1@99.889,70.405 100.646,70.405 ; 104.002,71.802 104.661,72.461 105.439,72.461 105.65,72.25 IC13.23@106.15,72.25
  Top Layer w0.152: 100.646,70.405 102.043,71.802 104.002,71.802
NetIC13_24: IC13.24 R117.1 | length 3.7
  Top Layer w0.152: R117.1@103.572,70.405 104.224,71.056 104.224,71.524 104.78,72.08 105.32,72.08 105.65,71.75 IC13.24@106.15,71.75
NetIC13_32: IC13.32 R128.2 | length 2.9
  Top Layer w0.147: R128.2@103.572,68.5 104.086,67.985 104.984,67.985 105.22,67.75 IC13.32@106.15,67.75
NetIC13_33: IC13.33 R126.2 | length 6.8
  Top Layer w0.152: R126.2@99.889,68.5 100.705,67.683 104.859,67.683 105.292,67.25 IC13.33@106.15,67.25
NetIC13_36: IC13.36 R124.2 | length 2.7
  Top Layer w0.152: R124.2@103.572,66.595 104.467,65.7 IC13.36@105.95,65.7
NetIC13_38: IC13.38 R119.2 | length 6.5
  Top Layer w0.147: R119.2@99.889,65.325 100.575,65.325 101,64.9 104.264,64.9 104.414,64.75 104.782,64.75
  Top Layer w0.152: 104.782,64.75 IC13.38@106.15,64.75
NetIC13_39: IC13.39 R118.2 | length 2.4
  Top Layer w0.152: R118.2@103.767,64.25 IC13.39@106.15,64.25
NetIC13_40: IC13.40 R121.2 | length 6.3
  Top Layer w0.152: R121.2@100.016,63.293 104.093,63.293 104.55,63.75 IC13.40@106.15,63.75
NetIC13_41: IC13.41 R116.2 | length 6.9
  Top Layer w0.152: R116.2@99.889,61.769 101.032,62.912 104.221,62.912 104.559,63.25 IC13.41@106.15,63.25
NetIC13_42: IC13.42 R114.2 | length 2.9
  Top Layer w0.147: R114.2@103.621,61.807 104.564,62.75 105.477,62.75
  Top Layer w0.152: 105.477,62.75 IC13.42@106.15,62.75
NetIC13_48: IC13.48 R129.1 | length 3.2
  Top Layer w0.152: R129.1@106.7,58.426 108,59.726 108,60.025 108.45,60.475 IC13.48@108.45,60.95
NetIC13_49: IC13.49 R127.1 | length 2.4
  Top Layer w0.152: v1(108.6,59.6) 108.6,60.072 108.95,60.422 IC13.49@108.95,60.95
  Bottom Layer w0.152: R127.1@108.5,58.726 v1@108.5,59.6
NetIC13_50: IC13.50 R122.1 | length 3
  Top Layer w0.152: R122.1@108.3,58.4 109.2,59.3 109.2,60.09 109.45,60.34 IC13.50@109.45,60.95
NetIC13_51: IC13.51 R125.1 | length 2.5
  Top Layer w0.152: v1(109.8,59.6) 109.8,60.2 109.95,60.35 IC13.51@109.95,60.95
  Bottom Layer w0.152: R125.1@109.8,58.526 v1(109.8,59.6)
NetIC13_52: IC13.52 R123.1 | length 2.7
  Top Layer w0.152: R123.1@109.9,58.426 110.421,58.946 IC13.52@110.421,60.921
NetL1_1: L1.1 X5.2 | length 7.3
  Top Layer w1.016: L1.1@37.91,46.24 X5.2@45.2,46.24
NetL1_2: L1.2 L10.1 | length 5.3
  Top Layer w1.016: L1.2@33.855,47.745 33.855,49 v5(33.9,49) v5@33.95,49 ; L1.2@34.4,47.3 34.4,48.55 v5@33.95,49 ; L1.2@35,48 v5(35,49) v5@33.95,49
NetL1_3: L1.3 L8.1 | length 5.6
  Top Layer w1.016: L1.3@33.8,34.6 v5(33.8,33.6) v5@34.85,33.6 ; L1.3@34.4,35.3 34.4,34.05 v5@34.85,33.6 ; L1.3@34.945,34.855 34.945,33.6 v5(34.9,33.6) v5@34.85,33.6
  Bottom Layer w1.016: L8.1@33.8,37.3 L8.1@34,37.5
NetL1_4: L1.4 X10.2 | length 7.3
  Top Layer w1.016: L1.4@37.91,36.36 X10.2@45.2,36.36
NetR2_1: R2.1 X1.A5 | length 6.6
  Top Layer w0.203: v2(142.161,31.089) 143.189,31.089 143.45,31.35 X1.A5@144.42,31.35
  Top Layer w0.381: R2.1@141.671,28 v2(142.595,28)
  Bottom Layer w0.254: v2(142.161,31.089) 142.161,28.439 v2@142.595,28.005
NetR15_1: R15.1 T3.2 T8.1 | length 6.2
  Bottom Layer w0.254: T3.2@56,48.85 T8.1@58,48.85 59.5,48.85 60.65,47.7 R15.1@61.75,47.7
NetR35_1: R35.1 T10.1 | length 1.7
  Top Layer w0.381: T10.1@44,28.75 44.174,28.924 R35.1@44.174,30.4
NetR36_2: R36.2 T10.2 | length 2.3
  Top Layer w0.381: R36.2@43.65,24.7 44,25.05 T10.2@44,26.85
NetR52_2: R52.2 S1.1 | length 2.9
  Top Layer w0.254: v1(62.7,59.425) 62.7,61.195 S1.1@62.73,61.225
  Bottom Layer w0.254: R52.2@62.7,58.351 v1(62.7,59.425)
NetR53_2: R53.2 S1.2 | length 2.9
  Top Layer w0.254: v1(65.24,59.425) S1.2@65.24,61.195
  Bottom Layer w0.254: R53.2@65.2,58.351 65.24,58.391 v1(65.24,59.425)
NetR54_2: R54.2 S1.3 | length 2.9
  Top Layer w0.254: v1(67.76,59.425) S1.3@67.76,61.195
  Bottom Layer w0.254: v1(67.76,59.425) 67.76,58.391 R54.2@67.8,58.351
NetR55_2: R55.2 S1.4 | length 2.8
  Top Layer w0.254: v1(70.3,59.425) S1.4@70.3,61.195
  Bottom Layer w0.254: R55.2@70.3,58.351 v1(70.3,59.425)
NetR56_2: R56.2 S1.5 | length 2.9
  Top Layer w0.254: v1(72.84,59.425) S1.5@72.84,61.195
  Bottom Layer w0.254: v1(72.84,59.425) 72.84,58.411 R56.2@72.9,58.351
NetR57_2: R57.2 S1.6 | length 2.9
  Top Layer w0.254: v1(75.36,59.425) S1.6@75.36,61.195
  Bottom Layer w0.254: v1(75.36,59.425) 75.36,58.391 R57.2@75.4,58.351
NetR58_2: R58.2 S1.7 | length 2.8
  Top Layer w0.254: v1(77.9,59.425) S1.7@77.9,61.195
  Bottom Layer w0.254: R58.2@77.9,58.351 v1(77.9,59.425)
NetR59_2: R59.2 S1.8 | length 2.9
  Top Layer w0.254: v1(80.44,59.425) S1.8@80.44,61.195
  Bottom Layer w0.254: R59.2@80.4,58.351 80.44,58.391 v1(80.44,59.425)
NetR76_2: R76.2 T4.1 | length 1.6
  Top Layer w0.254: R76.2@94,76.475 T4.1@95.576,76.475
NetR90_1: R90.1 X7.P10 | length 1.8
  Bottom Layer w0.203: R90.1@129.525,68.7 X7.P10@131.355,68.7
NetR91_1: R91.1 X7.P12 | length 1.8
  Bottom Layer w0.203: R91.1@129.525,60.3 X7.P12@131.345,60.3
NetR94_1: R94.1 R100.2 R106.2 | length 4.1
  Top Layer w0.178: R100.2@89.925,72.6 90.626,73.3 92.725,73.3 R106.2@93.426,72.6
NetR95_1: R95.1 R101.2 R107.2 | length 4.1
  Top Layer w0.178: R101.2@89.925,70.8 90.626,71.5 92.725,71.5 R107.2@93.426,70.8
NetR96_1: R96.1 R102.2 R108.2 | length 4.1
  Top Layer w0.178: R102.2@89.925,69 90.626,69.7 92.725,69.7 R108.2@93.426,69
NetR97_1: R97.1 R103.2 R109.2 | length 4.1
  Top Layer w0.178: R103.2@89.925,67.2 90.626,67.9 92.725,67.9 R109.2@93.426,67.2
NetR98_1: R98.1 R104.2 R110.2 | length 4.1
  Top Layer w0.178: R104.2@89.925,63.6 90.626,64.3 92.725,64.3 R110.2@93.426,63.6
NetR99_1: R99.1 R105.2 R111.2 | length 4.1
  Top Layer w0.178: R105.2@89.925,65.4 90.626,66.1 92.725,66.1 R111.2@93.426,65.4
NetR132_1: R132.1 R138.2 R144.2 | length 4.1
  Top Layer w0.178: R138.2@89.925,58.9 90.626,59.6 92.725,59.6 R144.2@93.426,58.9
NetR133_1: R133.1 R139.2 R145.2 | length 4.1
  Top Layer w0.178: R139.2@89.925,57.1 90.626,57.8 92.725,57.8 R145.2@93.426,57.1
NetR134_1: R134.1 R140.2 R146.2 | length 4.1
  Top Layer w0.178: R140.2@89.925,55.3 90.625,56 92.725,56 R146.2@93.426,55.3
NetR135_1: R135.1 R141.2 R147.2 | length 4.1
  Top Layer w0.178: R141.2@89.925,53.5 90.625,54.2 92.725,54.2 R147.2@93.426,53.5
NetR136_1: R136.1 R142.2 R148.2 | length 4.1
  Top Layer w0.178: R142.2@89.925,49.9 90.626,50.6 92.725,50.6 R148.2@93.426,49.9
NetR137_1: R137.1 R143.2 R149.2 | length 4.1
  Top Layer w0.178: R143.2@89.925,51.7 90.626,52.4 92.725,52.4 R149.2@93.426,51.7
NetR158_2: R158.2 X8.2 | length 2.8
  Top Layer w0.381: X8.2@108.823,30.2 v3(110.401,30.2)
  Bottom Layer w0.508: R158.2@110.4,29 v3(110.401,30.2)
NetR159_2: R159.2 X8.7 | length 2.9
  Top Layer w0.381: X8.7@108.785,36.6 v3(110.401,36.6)
  Bottom Layer w0.508: v3(110.401,36.6) R159.2@110.4,37.9
NRST: C96.1 IC5.10 S3.1 S3.3 X11.5 | length 35
  Top Layer w0.203: S3.3@69,51.3 S3.1@72.4,51.3 72.4,49.9 72.8,49.5 v1(75,49.5) 76,49.5 76.25,49.25 IC5.10@76.25,47.925 v1(76.25,45.2) ; v1(84.9,36.8) 84.9,33.2 85.06,33.04 X11.5@86.4,33.04
  Bottom Layer w0.203: v1(76.25,45.2) 76.25,39.75 76.6,39.4 83.5,39.4 84.9,38 v1(84.9,36.8)
  Bottom Layer w0.254: C96.1@75,48.526 v1@75,49.4
OUTM0: IC4.25 R13.2 R32.2 RSL0.2 T9.2 X10.1 | length 40
  Top Layer w0.229: IC4.25@69.9,17.75 71.35,17.75 v1(72.4,16.7)
  Top Layer w0.254: v1(80.9,12) RSL0.2@81.95,12
  Top Layer w1.27: RSL0.2@81.95,12 83.4,12 84,12.6 84,28.1 82.3,29.8 v1(82.3,33.1) v1(82.3,33.8) v1(82.3,34.5) v1(82.3,35.2)
  Signal Layer 3 w0.305: v1(72.4,16.7) 77.1,12 v1(80.9,12)
OUTP0: C34.1 C35.1 C36.2 C110.2 D10.2 FB10.1 IC4.1 T2.1 T2.2 T2.3 T3.3 T6.3 | length 24.2
  Top Layer w0.203: 62,24.04 62,23.6 62.35,23.25 IC4.1@63.1,23.25
  Top Layer w0.254: T2.1@52.475,40.03 54.37,40.03 54.9,39.5 54.9,30.1 59.9,25.1 60.94,25.1 62,24.04
  Top Layer w0.381: C110.2@51.4,45.425 C110.2@51.796,45.425
  Top Layer w0.508: C110.2@51.4,45.35 51.721,45.35 C110.2@51.796,45.425
  other v1: 51.4,41.3 52.2,41.3 51.4,42.1 52.2,42.1 52.2,42.9 52.2,43.7
P0_COL: IC13.70
P0_CRS: IC13.69
P0_DUPLEX: IC13.54 R104.1 | length 26.4
  Top Layer w0.152: v1(111,59.6) 111,60 111.45,60.45 IC13.54@111.45,60.95
  Top Layer w0.3: v1(88.274,62.726) R104.1@88.274,63.6
  Bottom Layer w0.203: v1(88.274,62.726) 97.975,62.726 100.1,60.6 110,60.6 v1(111,59.6)
P0_INCLK: IC9.32 R55.1 R121.1 | length 51.8
  Top Layer w0.147: v1(97.3,63.5) R121.1@98.175,63.5
  Top Layer w0.254: IC9.32@55.05,63.25 55.8,63.25 55.885,63.165 59.329,63.165 59.764,63.6 v1(69.4,63.6) 81.655,63.6 82.155,63.1 v1(86.2,63.1)
  Bottom Layer w0.254: v1(69.4,63.6) 69.4,57.6 R55.1@70.3,56.7 ; v1(86.2,63.1) 87.6,64.5 96.3,64.5 v1(97.3,63.5)
P0_IND0: IC9.31 R56.1 R119.1 | length 52.4
  Top Layer w0.147: v1(71.6,63) 81.554,63 82.054,62.5 86.9,62.5 87.2,62.8 87.2,64.3 87.5,64.6 96.556,64.6 97.356,65.4 R119.1@98.2,65.4
  Top Layer w0.254: IC9.31@55.05,62.75 59.664,62.75 59.914,63 v1(71.6,63)
  Bottom Layer w0.254: v1(71.6,63) 72,62.6 72,57.6 R56.1@72.9,56.7
P0_IND1: IC9.30 R57.1 R118.1 | length 56.4
  Top Layer w0.147: v1(74.3,58.5) 80.9,58.5 84,61.6 96.338,61.6 96.7,61.962 96.7,63.9 97.139,64.339 100.436,64.339 100.684,64.092 R118.1@101.709,64.092
  Top Layer w0.254: IC9.30@54.35,62.05 54.35,59.15 55,58.5 v1(74.3,58.5)
  Bottom Layer w0.254: v1(74.3,58.5) 74.3,57.8 R57.1@75.4,56.7
P0_IND2: IC9.29 R58.1 R116.1 | length 51.1
  Top Layer w0.152: v1(76.775,57.8) 80.67,57.8 84.065,61.195 97.67,61.195 R116.1@98.175,61.7
  Top Layer w0.254: IC9.29@53.85,62.05 53.85,58.875 54.925,57.8 v1(76.775,57.8)
  Bottom Layer w0.254: v1(76.775,57.8) R58.1@77.875,56.7
P0_IND3: IC9.28 R59.1 R114.1 | length 73.8
  Top Layer w0.152: v1(79.3,57.1) 80.5,57.1 84.2,60.8 ; 84.2,60.8 100.974,60.8 ; 84.2,60.8 100.975,60.8 ; 100.974,60.8 R114.1@101.875,61.7 100.975,60.8
  Top Layer w0.254: IC9.28@53.35,62.05 53.35,58.676 54.926,57.1 v1(79.3,57.1)
  Bottom Layer w0.254: v1(79.3,57.1) 79.7,56.7 R59.1@80.4,56.7
P0_INDV: IC9.33 IC13.37 R54.1 | length 60.8
  Top Layer w0.147: v3@96.9,66.238 100.262,66.238 101.25,65.25 IC13.37@106.15,65.25
  Top Layer w0.254: IC9.33@55.05,63.75 55.95,63.75 56.1,63.6 59.034,63.6 59.634,64.2 v1(66.9,64.2) 81.83,64.2 82.13,63.9 v3(85.4,63.9)
  Bottom Layer w0.254: v1(66.9,64.2) 66.9,57.6 R54.1@67.8,56.7 ; v3(85.4,63.9) 87.7,66.2 v3(96.9,66.2)
P0_INER: IC9.34 IC13.46 R53.1 | length 79.6
  Top Layer w0.152: IC13.46@107.45,60.95 107.45,60.403 107.247,60.2 101.58,60.2 101.012,59.631 97.463,59.631 96.645,60.45 ; 84.75,60.45 v1(84.3,60) 84.75,60.45 ; 84.75,60.45 96.645,60.45 ; 84.75,60.45 96.645,60.45
  Top Layer w0.254: IC9.34@55.05,64.25 56.05,64.25 56.225,64.075 58.775,64.075 59.5,64.8 v1(64.3,64.8) v3(82.8,64.8)
  Bottom Layer w0.254: v1(64.3,64.8) 64.3,57.6 R53.1@65.2,56.7 ; v3(82.8,64.8) 83.6,64.8 83.9,64.5 83.9,62.4 84.3,62 v1(84.3,60)
P0_MDC: IC13.57 R151.2 TP8.1 | length 21.3
  Top Layer w0.152: R151.2@100.8,51.226 TP8.1@100.8,52.8 102.092,54.092 111.888,54.092 113.959,56.163 113.959,59.51 112.95,60.519 IC13.57@112.95,60.95
P0_MDIO: IC13.58 R150.1 TP7.1 | length 19.7
  Top Layer w0.152: R150.1@102.9,51.226 TP7.1@102.9,52.8 103.8,53.7 112.05,53.7 114.34,55.99 114.34,59.637 113.45,60.527 IC13.58@113.45,60.95
P0_OUT/REF_CLK_MODE0: IC9.38 R103.1 R124.1 | length 47.9
  Top Layer w0.147: R103.1@88.274,67.2 89.039,66.435 96.185,66.435 96.831,67.081 101.323,67.081 R124.1@101.809,66.595
  Top Layer w0.254: IC9.38@55.05,66.25 55.75,66.25 55.975,66.475 82.775,66.475 83.5,67.2 R103.1@88.274,67.2
P0_OUTD0_MODE1: IC9.39 R102.1 R126.1 | length 44.5
  Top Layer w0.152: R102.1@88.274,69 89.024,68.25 96.225,68.25 96.475,68.5 R126.1@98.175,68.5
  Top Layer w0.254: IC9.39@55.05,66.75 55.65,66.75 55.9,67 82.6,67 84.6,69 R102.1@88.274,69
P0_OUTD1_MODE2: IC9.40 R101.1 R128.1 | length 48.9
  Top Layer w0.147: R101.1@88.274,70.8 89.049,70.026 95.874,70.026 96.638,69.262 101.088,69.262 R128.1@101.6,68.75
  Top Layer w0.254: IC9.40@55.05,67.25 55.375,67.25 55.625,67.5 82.4,67.5 85.7,70.8 R101.1@88.274,70.8
P0_OUTD2_MODE3: IC9.1 R100.1 R130.1 | length 51.5
  Top Layer w0.147: R100.1@88.274,72.6 88.974,71.9 101.174,71.9 R130.1@101.875,72.6
  Top Layer w0.254: IC9.1@54.35,67.95 54.35,68.75 54.7,69.1 59.6,69.1 60.75,67.95 82.15,67.95 86.8,72.6 R100.1@88.274,72.6
P0_OUTD3: IC9.2 R52.1 R131.1 | length 61.7
  Top Layer w0.254: IC9.2@53.85,67.95 53.85,68.95 54.5,69.6 60.1,69.6 v1(60.85,68.85) 61.3,68.4 81.9,68.4 87.3,73.8 96.056,73.8 97.256,72.6 R131.1@98.175,72.6
  Bottom Layer w0.254: v1(60.85,68.85) 61.8,67.9 61.8,57.6 R52.1@62.7,56.7
P0_OUTDV: IC9.37 IC13.34 R152.2 TP9.1 | length 80.8
  Top Layer w0.147: v3(96.8,67.9) 97.319,67.381 104.734,67.381 105.365,66.75 IC13.34@106.15,66.75
  Top Layer w0.203: v1(85.1,59.5) 85.685,60.085 96.515,60.085 97.35,59.25 100.25,59.25 100.8,58.7 TP9.1@100.8,56.8
  Top Layer w0.254: IC9.37@55.05,65.75 55.906,65.75 56.13,65.974 83.074,65.974 83.5,66.4 v3(86,66.4) ; TP9.1@100.8,56.8 v1(102,56.8) R152.2@102.874,56.8
  Bottom Layer w0.254: v1(85.1,59.5) 85.1,61.923 84.4,62.623 84.4,64.8 v3(86,66.4) 87.5,67.9 v3(96.8,67.9)
P0_OUTER_SPEED: IC9.36 IC13.28 R105.1 | length 57.8
  Top Layer w0.147: v1(96.8,70) 97.157,69.643 102.956,69.643 103.186,69.413
  Top Layer w0.152: 103.186,69.413 105.398,69.413 105.735,69.75 IC13.28@106.15,69.75
  Top Layer w0.254: IC9.36@55.05,65.25 56.045,65.25 56.295,65.5 R105.1@88.274,65.5
  Bottom Layer w0.254: v1(83.9,65.544) 88.356,70 v1(96.8,70)
P1_COL: IC13.72
P1_CRS: IC13.73
P1_IND0: R117.2
P1_IND1: R115.2
P1_IND2: R113.2
P1_IND3: R112.2
P1_INDCLK: R120.2
P1_INDV: IC13.25 | length 1.3
  Top Layer w0.147: v1(105.012,71.548) 105.31,71.25 IC13.25@106.15,71.25
P1_INER: IC13.19
P1_MDC_DUPLEX: IC13.71 R142.1 | length 49.1
  Top Layer w0.147: R142.1@88.274,49.9 89.049,49.126 96.628,49.126 99.053,46.7 117.5,46.7 v1(119.2,48.4)
  Top Layer w0.178: IC13.71@118.25,63.75 119,63.75 119.2,63.55 v1(119.2,63.1)
  Bottom Layer w0.178: v1(119.2,48.4) v1(119.2,63.1)
P1_OUT/REF_CLK_MODE0: R122.2 R141.1 | length 23.5
  Top Layer w0.147: R141.1@88.274,53.5 89.049,52.726 ; 89.074,52.7 v1(97,52.7)
  Top Layer w0.152: v1(97,55.3) 106.825,55.3 R122.2@108.3,56.775
  Bottom Layer w0.147: v1(97,52.7) v1(97,55.3)
P1_OUTD0_MODE1: R123.2 R140.1 | length 22.9
  Top Layer w0.147: R140.1@88.274,55.3 89.049,54.526 97.951,54.526 98.225,54.8 107.925,54.8 R123.2@109.9,56.775
P1_OUTD1_MODE2: R125.2 R139.1 | length 34.5
  Top Layer w0.147: R139.1@88.274,57.1 89.049,56.326 v1(98.5,56.326)
  Bottom Layer w0.147: 99.799,56.326 v1(98.5,56.326) 99.799,56.326 ; 99.799,56.326 100.25,55.875 ; 99.799,56.326 100.25,55.875 ; 100.25,55.875 109,55.875 ; 100.25,55.875 109,55.875 ; 109,55.875 R125.2@109.9,56.775 109,55.875
P1_OUTD2_MODE3: R127.2 R138.1 | length 32.3
  Top Layer w0.147: R138.1@88.274,58.9 89.049,58.126 v1(98.5,58.126)
  Bottom Layer w0.147: 100.477,56.149 107.674,56.149 ; 100.477,56.149 v1(98.5,58.126) 100.477,56.149 ; 100.477,56.149 107.674,56.149 ; 107.674,56.149 R127.2@108.3,56.775 107.674,56.149
P1_OUTD3: R129.2
P1_OUTDV: IC13.53
P1_OUTER_MDIO_SPEED: IC13.44 R143.1 | length 28.1
  Top Layer w0.147: R143.1@88.274,51.7 89.049,50.926 v1(97.8,50.926) ; IC13.44@105.95,61.75 IC13.44@106.15,61.75
  Top Layer w0.152: v1(97.8,60.2) 101,60.2 101.4,60.6 104.8,60.6 IC13.44@105.95,61.75
  Bottom Layer w0.147: v1(97.8,50.926) v1(97.8,60.2)
PME_MODE: IC1.43 TP1.1 | length 10.9
  Top Layer w0.25: IC1.43@123.15,36 v2@123.15,37.205
  Top Layer w0.381: TP1.1@119.2,44.505 v3(120.4,44.505)
  Bottom Layer w0.25: v3(120.4,44.505) 121.6,43.305 121.6,38.805 v2(123.2,37.205)
PME_N/CONNECT: IC1.22 R8.1 | length 8
  Top Layer w0.203: IC1.22@125.15,29.2 125.15,28.36 125.425,28.085 126.17,28.085 126.9,27.355 126.9,23.583 127.228,23.255 R8.1@127.975,23.255
POWER/DATA_N: D15.1 D16.2 D30.2 L6.4 X2.2 X3.1 | length 51.9
  Top Layer w1.016: X2.2@12.45,42.3 L6.4@20.63,42.3
  Signal Layer 3 w0.762: X3.1@8.2,55.8 8.2,51.7 11.2,48.7 14.712,48.7 17,46.412 17,43.2 16.1,42.3 X2.2@12.45,42.3
  Bottom Layer w0.762: D30.2@9,44.2 10.55,44.2 X2.2@12.45,42.3 17.6,42.3 18.7,41.2 D16.2@18.7,32.1 D16.2@18.7,31.6
POWER/DATA_P: D11.2 D12.1 D30.1 L6.3 X2.1 X3.2 | length 54
  Top Layer w1.016: X2.1@12.45,39.5 22.358,39.5 23.17,40.312 L6.3@23.17,42.15
  Signal Layer 3 w0.762: X3.2@8.2,59.3 10.473,57.027 10.473,51.413 11.936,49.95 15.35,49.95 18.25,47.05 18.25,40.804 16.946,39.5 X2.1@12.45,39.5
  Bottom Layer w0.762: D11.2@6.9,31.6 D11.2@6.9,32.1 ; D11.2@7.3,32.255 D30.1@7.3,37.6 ; D30.1@9,37.6 10.55,37.6 X2.1@12.45,39.5
R\E\S\E\T\: IC9.5 IC10.2 IC13.12 R72.2 T4.3 | length 78.3
  Top Layer w0.152: v1(100.1,78.1) 101.1,79.1 106.677,79.1 107.247,78.53 107.247,77.768 108.898,76.117 111.021,76.117 111.95,75.188 IC13.12@111.95,73.05
  Top Layer w0.254: IC9.5@52.35,67.95 52.35,69.75 v1(53.2,70.6) ; IC10.2@96.6,80.6 T4.3@96.6,78.8 97.3,78.1 v1(100.1,78.1)
  Bottom Layer w0.254: v1(53.2,70.6) 53.2,72.856 53.544,73.2 86,73.2 87.1,74.3 99.574,74.3 100.1,74.826 v1(100.1,78.1)
RBIAS: IC13.80 R83.1 | length 4.3
  Top Layer w0.152: IC13.80@118.308,68.25 118.9,68.25 119.05,68.4 120.3,68.4 120.5,68.2 120.5,67.5 R83.1@121.4,66.6
RXA_N: C102.1 IC13.77 R157.1 R199.2 X8.9 | length 56
  Top Layer w0.154: IC13.77@118.25,66.75 118.652,66.75 118.762,66.86 119.134,66.86 119.6,66.394 v2(119.6,66.3)
  Top Layer w0.254: C102.1@96.826,36.7 96.826,38.2 97.826,38.2 98.181,37.845 X8.9@99.99,37.845
  Top Layer w0.381: X8.9@100.009,37.864 v3(101.591,37.864)
  Bottom Layer w0.154: v3(101.591,37.864) 100.686,37.864 100.25,38.3 100.25,39.6 100.7,40.05 112.951,40.05 116.184,43.284 116.184,64.487 116.397,64.7 118.097,64.7 118.471,65.073 118.471,66.37 118.61,66.51 119.391,66.51 v2(119.6,66.3)
  Bottom Layer w0.254: v3@101.591,37.9 102.921,37.9 R199.2@102.951,37.87
RXA_P: C101.1 IC13.78 R156.1 R198.2 X8.11 | length 58.1
  Top Layer w0.154: IC13.78@118.25,67.25 118.652,67.25 118.762,67.14 119.46,67.14 v2(119.6,67)
  Top Layer w0.254: C101.1@96.826,33.644 R156.1@96.826,34.944 ; R156.1@96.826,35.305 X8.11@99.99,35.305
  Top Layer w0.381: X8.11@100.009,35.324 v3(101.591,35.324)
  Bottom Layer w0.154: v3@101.591,35.326 101.591,36.509 99.97,38.131 99.97,39.716 100.584,40.331 112.834,40.331 115.904,43.4 115.904,64.603 116.281,64.981 117.981,64.981 118.19,65.189 118.19,66.486 118.494,66.79 119.391,66.79 v2(119.6,67)
  Bottom Layer w0.254: v3@101.591,35.326 102.876,35.326 R198.2@102.95,35.4
RXB_N: C88.1 D26.7 IC13.84 R80.1 X7.P6 | length 37.6
  Top Layer w0.147: IC13.84@118.25,70.25 118.775,70.25 118.824,70.201 118.828,70.204 120.397,70.204 120.4,70.207 ; 121.019,70.201 124.237,70.201 124.574,69.864 124.574,65.726 124.9,65.4 D26.7@127.875,65.4 128.678,65.4 129.404,64.674 130.9,64.674 131.074,64.674 131.074,65.174 131.421,65.174 131.421,64.674 131.768,64.674 131.768,65.174 132.116,65.174 132.116,64.674 132.463,64.674 132.463,65.174 132.81,65.174 132.81,64.674 133.158,64.674 133.158,65.174 133.505,65.174 133.505,64.674 133.852,64.674 133.852,65.174 134.2,65.174 134.2,64.674 134.3,64.674 134.589,64.674 135.369,63.895 X7.P6@138.75,63.895
  Top Layer w0.154: 120.4,70.207 v2(120.56,70.367) 120.86,70.367 121.019,70.207
  Bottom Layer w0.154: v2(120.56,70.367) 121.341,70.367 C88.1@121.775,70.8
  Bottom Layer w0.203: R80.1@134.625,61.5 137.1,61.5 137.5,61.9 137.5,62.645 X7.P6@138.75,63.895
RXB_P: C87.1 D26.4 IC13.83 R79.1 X7.P4 | length 38.2
  Top Layer w0.147: IC13.83@118.25,69.75 118.649,69.75 118.825,69.926 120.4,69.926 ; 120.86,69.767 121.019,69.926 124.124,69.926 124.3,69.75 124.3,65.612 124.912,65 D26.4@126.925,65 128.69,65 129.29,64.4 134.476,64.4 135.255,63.621 137.579,63.621 138.3,62.9 139.3,62.9 139.8,63.4 139.8,65.385 X7.P4@138.75,66.435
  Top Layer w0.154: 120.4,69.926 v2(120.56,69.767) 120.86,69.767
  Bottom Layer w0.154: v2(120.56,69.767) 121.296,69.767 121.663,69.4 C87.1@121.775,69.4
  Bottom Layer w0.203: R79.1@134.625,63.1 135.525,64 137.2,64 137.5,64.3 137.5,65.185 X7.P4@138.75,66.435 X7.P4@138.785,66.4
SCCPI0: D18.2 IC5.20 R26.2 SCCPI.1 T6.2 | length 22.1
  Top Layer w0.254: SCCPI.1@70.3,43.8 v1(71.6,43.8) 72.25,43.15 IC5.20@73.975,43.15
  Bottom Layer w0.254: T6.2@56,45.35 56,43.974 55.725,43.7 R26.2@55.926,43.7 D18.2@57.45,43.7 58.15,44.4 60.768,44.4 61.368,43.8 v1(71.6,43.8)
SCCPO0: IC5.19 R27.2 SCCPO.1 | length 15.2
  Top Layer w0.254: SCCPO.1@70.3,46.2 71.1,45.4 v1(71.6,45.4) 72.3,44.7 72.3,43.9 72.55,43.65 IC5.19@73.975,43.65
  Bottom Layer w0.203: R27.2@63.926,49.8 68.007,49.8 71.6,46.207 v1(71.6,45.4)
SHIELD: C19.2 C41.1 C90.1 C91.1 C92.1 C93.1 C94.1 C95.1 C106.2 C107.2 C108.2 C109.2 C116.1 C127.2 D2.3 D3.3 D4.3 D22.1 D29.2 D30.3 D33.1 D36.1 H1.0 H2.0 H3.0 H4.0 H5.0 R19.2 R20.2 R21.2 R22.2 R23.2 R42.2 VAR1.2 VAR2.1 X2.SH X3.3 X7.B1 X7.B2 X7.P8 | length 110.1
  Top Layer w0.254: D2.3@141.275,30.8 v2@141.275,31.175 ; D4.3@141.275,32.8 v2@141.275,33.175 ; D3.3@141.275,34.8 v2@141.275,35.175
  Signal Layer 3 w0.635: v2(141.3,31.2) v2(141.3,33.2) v2(141.3,35.2) 141.3,37.155 144.169,40.024 151.6,40.024
  Bottom Layer w0.381: v2(141.3,31.2) v2(141.3,33.2) v2(141.3,35.2)
  Bottom Layer w1.016: 12.124,1.45 13,2.326 ; 13,12.7 13,2.326 ; 13.875,1.45 13,2.326 ; D36.1@23.7,24.2 29.6,18.3 C107.2@29.6,13.354 ; D36.1@24.4,24.5 30.4,18.5 30.4,14.8 ; 28.612,1.188 29.6,2.176 29.6,2.5 ; C107.2@29.526,13.279 C107.2@29.6,13.354 ; 30.4,14 31.2,14.8 ; 30.4,15.6 31.2,14.8 ; v1@31.05,1.05 29.6,2.5 ; 31.7,1.45 30.4,2.75 30.4,13.279 30.4,14.8 ; C108.2@34.375,17.4 34.375,15.7 ; X7.P8@138.75,61.355 140.727,61.355 ; 141.472,60.61 140.727,61.355 ; 141.472,62.1 140.727,61.355 ; 29.6,2.5 C107.2@29.6,13.354 ; 30.4,14.8 31.2,14.8 ; 31.2,14.8 33.474,14.8 ; 33.474,14.8 34.375,15.7 ; 33.474,14.8 C109.2@34.375,14.8 34.375,15.7
  Bottom Layer w1.6: 4.423,39.9 5.423,40.9 ; 4.423,41.9 5.423,40.9 ; D30.3@9,40.9 5.423,40.9
  other v1: 12.4,1 22.4,1 31,1 41,1 51,1 61,1 71,1 81,1 91,1 101,1 111,1 121,1 130.907,1 140,1 1,7.5 149,7.5 154,12.5 149,17.5 145.6,20 146.3,20 148.3,20 149,20 151,20 151.7,20 154,22.5 1,25.4 154,32.545 1,35.4 154,42.5 1,45.416 154,52.5 1,55.4 149,57.5 144,62.5 154,62.5 14,65.4 14.7,65.4 6.1,66.5 6.8,66.5 8.8,66.5 9.5,66.5 11.4,66.5 12.1,66.5 1,67.5 149,67.5 154,72.5 1,77.5 149,77.5 11,85.5 21,85.5 41,85.5 51,85.5 61,85.5 71,85.5 81,85.5 91,85.5 101,85.5 110.979,85.5 120.95,85.5 130.976,85.5 141,85.5
  other v4: 4,1.7 151,1.7 2.374,2.374 5.626,2.374 149.374,2.374 152.626,2.374 1.7,4 6.3,4 148.7,4 153.3,4 2.374,5.626 5.626,5.626 149.374,5.626 152.626,5.626 4,6.3 151,6.3 4,47.4 2.374,48.074 5.626,48.074 1.7,49.7 6.3,49.7 2.374,51.326 5.626,51.326 4,52 4,80.2 151,80.2 2.374,80.874 5.626,80.874 149.374,80.874 152.626,80.874 1.7,82.5 6.3,82.5 148.7,82.5 153.3,82.5 2.374,84.126 5.626,84.126 149.374,84.126 152.626,84.126 4,84.8 151,84.8
SPI2_MISO: IC4.10 IC5.26 R3.2 | length 49
  Top Layer w0.203: v1(58,15.1) R3.2@59.1,15.1 ; R3.2@59.1,15.1 60.279,16.278 60.279,17.753 61.275,18.75 IC4.10@63.1,18.75 ; IC5.26@75.75,39.875 75.75,38.1 v1(76.05,37.8)
  Bottom Layer w0.203: v1(58,15.1) 62.7,15.1 68.671,15.1 71.1,17.529 71.1,21.3 72.792,22.992 74.5,22.992 75.606,24.098 75.606,27.902 74.6,28.908 74.6,34 76.9,36.3 76.9,37.5 76.6,37.8 v1@76,37.8
SPI2_MOSI: IC4.9 IC5.27 | length 47.9
  Top Layer w0.203: v1(58,16.1) 59.4,16.1 59.8,16.5 59.8,18.2 60.85,19.25 IC4.9@63.1,19.25 ; v1(76.2,36.8) 76.7,37.3 76.7,38.1 76.25,38.55 IC5.27@76.25,39.875
  Bottom Layer w0.203: v1(58,16.1) 58.6,15.5 62.4,15.5 68.505,15.5 70.7,17.695 70.7,21.466 72.627,23.392 74.335,23.392 75.206,24.264 75.206,27.736 74.2,28.742 74.2,34.226 76.2,36.225 v1(76.2,36.8)
SPI2_NSS: IC4.12 IC5.24 | length 38.1
  Top Layer w0.203: v1(61.8,17.3) 62.25,17.75 IC4.12@63.1,17.75 ; IC5.24@73.975,41.15 74,41.125 v1(74,40.4)
  Bottom Layer w0.203: v1@62,17.3 v1(61.8,17.3) 62.792,16.308 68.17,16.308 69.892,18.03 69.892,21.8 72.292,24.2 74,24.2 74.399,24.598 74.399,27.401 73.392,28.408 73.392,34.6 74.6,35.808 74.6,39.8 v1(74,40.4)
SPI2_SCK: IC4.11 IC5.25 | length 39.7
  Top Layer w0.203: v1(61,16.7) 61,17.684 61.566,18.25 IC4.11@63.1,18.25 ; v1@75.2,37.1 75.25,37.15 IC5.25@75.25,39.875
  Bottom Layer w0.203: v1(61,16.7) 61.804,15.896 68.341,15.896 70.304,17.859 70.304,21.63 72.463,23.788 74.171,23.788 74.81,24.428 74.81,27.572 73.804,28.578 73.804,34.43 75.3,35.925 v1@75.3,37.05
  other v1: 75.3,37.1
SWCLK: IC5.36 R33.2 X11.2 | length 24.1
  Top Layer w0.203: IC5.36@80.75,39.875 80.75,38.75 81,38.5 83.8,38.5 84.8,37.5 87.6,37.5 87.997,37.103 87.997,27.017 X11.2@86.4,25.42
  Bottom Layer w0.203: X11.2@86.4,25.42 86.455,25.475 R33.2@89.1,25.475
SWDIO: IC5.35 X11.4 | length 14.5
  Top Layer w0.203: IC5.35@80.25,39.875 80.25,38.5 80.65,38.1 83.6,38.1 84.2,37.5 84.2,31.2 84.9,30.5 X11.4@86.4,30.5
SWO: X11.6
TEST: IC1.34 R12.1 | length 8.8
  Top Layer w0.203: IC1.34@126.8,34.35 132.895,34.35 133.225,34.68 134.251,34.68 R12.1@135.125,35.555
TR0_N: IC1.2 R161.1 X8.3 | length 24.6
  Top Layer w0.154: v2(112.68,35.959) 113.04,35.959 113.201,36.119 117.524,36.119 118.684,34.96 119.463,34.96 119.573,34.85 IC1.2@120,34.85
  Top Layer w0.381: v3(107.159,31.476) X8.3@108.741,31.476
  Bottom Layer w0.154: v3(107.159,31.476) 107.159,30.492 107.406,30.244 108.07,30.244 109.226,31.4 113.304,31.4 113.72,31.816 113.72,35.98 113.582,36.118 113.2,36.118 113.04,35.959 v2(112.68,35.959)
  Bottom Layer w0.254: R161.1@105.726,31.476 v3(107.159,31.476)
TR0_P: IC1.1 R160.1 X8.1 | length 24.9
  Top Layer w0.154: v2(112.68,36.559) 113.041,36.559 113.2,36.4 117.64,36.4 118.8,35.24 119.463,35.24 119.573,35.35 IC1.1@120,35.35
  Top Layer w0.381: v3(107.159,28.936) X8.1@108.741,28.936
  Bottom Layer w0.154: v3(107.159,28.936) 109.342,31.119 113.42,31.119 114.001,31.7 114.001,36.096 113.918,36.179 113.698,36.399 113.201,36.399 113.041,36.559 v2(112.68,36.559)
  Bottom Layer w0.254: R160.1@105.686,28.936 v3(107.159,28.936)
